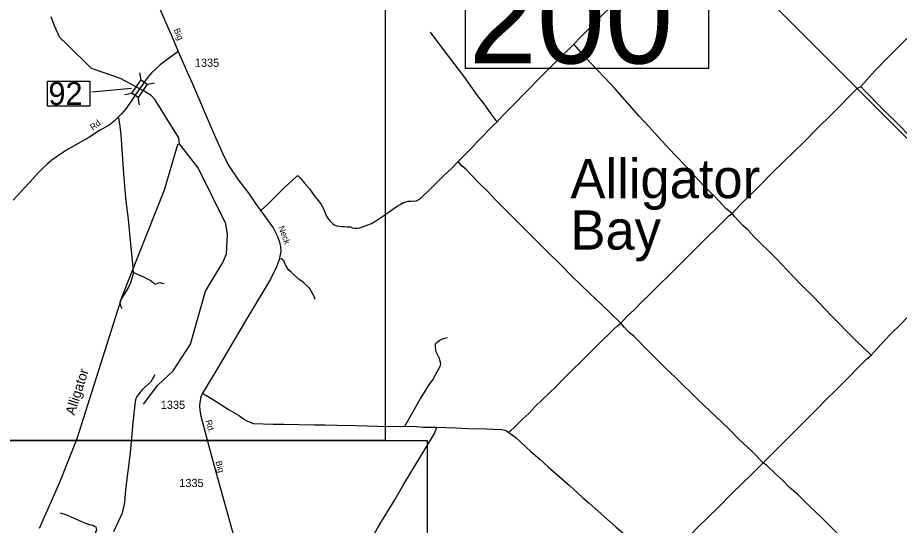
# Model space of a CAD drawing. Extents: x 2104537 to 2336408, y 34176 to 229611.
# Drawn here: x 2160349 to 2173826, y 123300 to 131059 of the extents above; entities that cross this region are included whole.
import ezdxf

# ---------------------------------------------------------------- set-up
doc = ezdxf.new("R2010")
doc.units = 0
for name, color, linetype in [('Exist Hydrographic Bay Label', 7, 'Continuous'), ('Exist Hydrographic Creek Single Shore', 7, 'Continuous'), ('Exist Hydrographic Misc Water Feature', 7, 'Continuous'), ('Exist Road Non-System Type 51', 7, 'Continuous'), ('Exist Road Secondary Structure Standard Bridge CELL', 7, 'Continuous'), ('Exist Road Secondary Structure Standard Bridge Number Label', 7, 'Continuous'), ('Exist Road Secondary Type 51 Attributed', 7, 'Continuous'), ('Exist Road Secondary Type 51 Label', 7, 'Continuous'), ('Exist Road Secondary Type 51 Number Label', 7, 'Continuous'), ('Exist Utilities Electrical Transmission Line', 7, 'Continuous'), ('Map Preparation Inset Cut Line', 7, 'Continuous'), ('Old_Level_32', 7, 'Continuous')]:
    doc.layers.add(name, color=color, linetype=linetype)

msp = doc.modelspace()

# ---------------------------------------------------------------- linework, layer by layer
at = {"layer": 'Exist Hydrographic Creek Single Shore'}
for points in [[(2162824, 129129), (2162812, 129223), (2162699, 129399), (2162453, 129802), (2162390, 129870), (2162282, 129937), (2161919, 130128), (2161480, 130281), (2161094, 130657), (2160995, 130756), (2160915, 130934), (2160861, 131074)], [(2160682, 123259), (2160994, 123961), (2161257, 124629), (2161945, 126800), (2162594, 128428), (2162799, 129120), (2162824, 129129)]]:
    msp.add_lwpolyline(points, dxfattribs=at)
at = {"layer": 'Exist Hydrographic Misc Water Feature'}
msp.add_lwpolyline([(2162271, 125150), (2162494, 125445), (2162726, 125663), (2162991, 126071), (2163219, 126881), (2163483, 127315), (2163541, 127449), (2163556, 127750), (2163530, 127908), (2163109, 128763), (2162824, 129129)], dxfattribs=at)
at = {"layer": 'Exist Road Non-System Type 51'}
for points in [[(2168849, 130656), (2168946, 130758), (2169084, 130892), (2169224, 131036), (2169477, 131283), (2169599, 131405), (2169858, 131652), (2169938, 131732), (2169974, 131760)], [(2173237, 130008), (2173449, 130246), (2173666, 130465), (2173780, 130585), (2174075, 130875), (2174161, 130965), (2174337, 131140), (2174389, 131188), (2174553, 131354), (2174594, 131391)], [(2167679, 129467), (2167587, 129587), (2167481, 129741), (2167380, 129869), (2167186, 130142), (2166779, 130678), (2166661, 130839)], [(2167679, 129467), (2167771, 129567), (2167970, 129766), (2168072, 129874), (2168393, 130203), (2168593, 130399), (2168849, 130656)], [(2171273, 128064), (2171176, 128144), (2171005, 128324), (2170933, 128390), (2170851, 128472), (2170763, 128571), (2170663, 128677), (2170583, 128767), (2170394, 128961), (2170192, 129184), (2170086, 129296), (2169998, 129396), (2169849, 129556), (2169481, 129971), (2169321, 130143), (2169210, 130254), (2169034, 130446), (2168849, 130656)], [(2171273, 128064), (2171391, 128200), (2171685, 128485), (2171894, 128697), (2172365, 129156), (2172571, 129363), (2172796, 129583), (2173181, 129975)], [(2173181, 129975), (2173185, 129980), (2173237, 130008)], [(2175369, 127892), (2175237, 128004), (2174529, 128709), (2174185, 129038), (2173845, 129395), (2173578, 129653), (2173292, 129944), (2173237, 130008)], [(2161893, 129528), (2161912, 129401), (2161925, 129269), (2161967, 128671), (2161994, 128369), (2162005, 128256), (2162037, 127982), (2162058, 127758), (2162106, 127298), (2162110, 127238), (2162109, 127196), (2162119, 127164)], [(2167084, 128860), (2167276, 129056), (2167376, 129167), (2167627, 129419), (2167679, 129467)], [(2164070, 128115), (2164170, 128204), (2164258, 128297), (2164426, 128461), (2164609, 128633), (2164621, 128643), (2164637, 128641), (2164667, 128613), (2164733, 128529), (2164816, 128438), (2164878, 128348), (2164964, 128240), (2164986, 128206), (2165022, 128138), (2165052, 128076), (2165072, 128026), (2165088, 127996), (2165123, 127954), (2165167, 127908), (2165185, 127892), (2165227, 127878), (2165297, 127868), (2165343, 127869), (2165387, 127863), (2165435, 127861), (2165469, 127849), (2165497, 127843), (2165547, 127841), (2165579, 127847), (2165704, 127892), (2165758, 127915), (2165810, 127942), (2165962, 128044), (2166046, 128106), (2166148, 128176), (2166194, 128206), (2166246, 128234), (2166316, 128255), (2166352, 128255), (2166394, 128259), (2166422, 128257), (2166448, 128261), (2166492, 128287), (2166621, 128401), (2166855, 128635), (2166923, 128702), (2166982, 128756), (2167084, 128860)], [(2169568, 126390), (2169267, 126683), (2169095, 126843), (2168822, 127110), (2168637, 127298), (2168462, 127465), (2167642, 128286), (2167526, 128413), (2167422, 128511), (2167272, 128665), (2167200, 128743), (2167140, 128793), (2167084, 128860)], [(2169568, 126390), (2169667, 126496), (2169771, 126594), (2169892, 126714), (2170000, 126824), (2170453, 127269), (2170852, 127670), (2171068, 127878), (2171154, 127966), (2171222, 128030), (2171273, 128064)], [(2173393, 125902), (2173157, 126130), (2172782, 126509), (2172508, 126799), (2172343, 126957), (2172201, 127102), (2171941, 127376), (2171600, 127715), (2171508, 127817), (2171432, 127885), (2171306, 128021), (2171273, 128064)], [(2173393, 125902), (2173485, 126004), (2173686, 126215), (2173858, 126385), (2174021, 126559), (2174271, 126804), (2174508, 127048), (2174706, 127247), (2174842, 127389), (2174929, 127475), (2174989, 127539), (2175133, 127679), (2175195, 127743), (2175261, 127804), (2175303, 127846)], [(2164896, 126753), (2164873, 126820), (2164810, 126925), (2164716, 127011), (2164654, 127059), (2164531, 127172), (2164489, 127206), (2164443, 127284), (2164420, 127345), (2164373, 127379)], [(2162119, 127164), (2162072, 127008), (2162047, 126948), (2162014, 126888), (2161980, 126837), (2161929, 126751), (2161917, 126725), (2161913, 126704), (2161918, 126669), (2161924, 126647), (2161942, 126615)], [(2162119, 127164), (2162274, 127100), (2162330, 127070), (2162374, 127045), (2162416, 127015), (2162441, 126989), (2162457, 126984), (2162502, 127004), (2162522, 127010), (2162552, 127002), (2162591, 126997)], [(2167855, 124721), (2167964, 124821), (2168058, 124915), (2168168, 125017), (2168260, 125115), (2168579, 125424), (2168697, 125546), (2169102, 125942), (2169208, 126051), (2169467, 126301), (2169525, 126355), (2169568, 126390)], [(2171744, 124258), (2171570, 124433), (2171378, 124613), (2171212, 124779), (2170745, 125222), (2170409, 125557), (2170238, 125719), (2170064, 125892), (2169996, 125956), (2169772, 126184), (2169690, 126254), (2169625, 126322), (2169568, 126390)], [(2166268, 124817), (2166504, 125228), (2166638, 125446), (2166696, 125526), (2166812, 125745), (2166818, 125773), (2166809, 125810), (2166791, 125862), (2166746, 125953), (2166742, 125991), (2166736, 126019), (2166738, 126073), (2166754, 126097), (2166803, 126132), (2166841, 126150), (2166920, 126170)], [(2171744, 124258), (2171876, 124390), (2171990, 124498), (2172554, 125065), (2172706, 125223), (2172844, 125356), (2172980, 125496), (2173267, 125782), (2173327, 125846), (2173393, 125902)], [(2162444, 125601), (2162387, 125495), (2162284, 125404), (2162244, 125360), (2162171, 125267), (2162155, 125241), (2162145, 125193), (2162109, 124866), (2162067, 124410), (2162000, 123847), (2161982, 123647), (2161969, 123571), (2161953, 123517), (2161948, 123485), (2161812, 123201)], [(2163188, 125310), (2163313, 125238), (2163580, 125068), (2163727, 124985), (2163818, 124920), (2163864, 124891), (2163956, 124857), (2164256, 124846), (2164416, 124848), (2164886, 124836), (2165042, 124835), (2165234, 124829), (2165528, 124826), (2165854, 124817), (2166204, 124812), (2166268, 124817)], [(2165682, 122845), (2165672, 122891), (2165680, 122935), (2165700, 122995), (2165742, 123071), (2165794, 123155), (2165855, 123265), (2166021, 123544), (2166115, 123692), (2166236, 123902), (2166722, 124705), (2166756, 124801)], [(2166268, 124817), (2166446, 124811), (2166540, 124803), (2166662, 124799), (2166756, 124801)], [(2166756, 124801), (2167046, 124792), (2167240, 124780), (2167516, 124776), (2167751, 124767), (2167794, 124757), (2167819, 124745), (2167855, 124721)], [(2167855, 124721), (2167969, 124637), (2168193, 124427), (2168332, 124312), (2168456, 124197), (2168786, 123910), (2168980, 123730), (2169085, 123637), (2169492, 123279), (2169976, 122859), (2170038, 122813), (2170121, 122739), (2170159, 122699)], [(2170159, 122699), (2170269, 122799), (2170387, 122919), (2170644, 123168), (2170740, 123266), (2171060, 123578), (2171275, 123795), (2171567, 124079), (2171744, 124258)], [(2173867, 122202), (2173755, 122318), (2173577, 122491), (2173387, 122689), (2173200, 122867), (2172774, 123282), (2172656, 123402), (2172441, 123603), (2172273, 123771), (2172149, 123877), (2172039, 123990), (2171937, 124082), (2171800, 124214), (2171744, 124258)], [(2161000, 123494), (2161094, 123459), (2161373, 123339), (2161463, 123306), (2161496, 123301), (2161519, 123287), (2161546, 123279), (2161554, 123233), (2161531, 123167), (2161478, 122984), (2161451, 122898), (2161401, 122750), (2161379, 122693), (2161326, 122563), (2161299, 122503), (2161256, 122418), (2161168, 122230), (2160944, 121739), (2160777, 121272), (2160720, 121101), (2160705, 121047)]]:
    msp.add_lwpolyline(points, dxfattribs=at)
at = {"layer": 'Exist Road Secondary Structure Standard Bridge CELL'}
for p, q in [((2162235, 130107), (2162215, 130218)), ((2162328, 130043), (2162440, 130063)), ((2161983, 129883), (2162094, 129903)), ((2162210, 129726), (2162189, 129838))]:
    msp.add_line(p, q, dxfattribs=at)
msp.add_lwpolyline([(2162094, 129903), (2162235, 130107), (2162330, 130042), (2162189, 129838)], close=True, dxfattribs=at)
at = {"layer": 'Exist Road Secondary Structure Standard Bridge Number Label'}
msp.add_line((2162088, 129975), (2161485, 129920), dxfattribs=at)
for points in [[(2167195, 131816), (2170910, 131816), (2170910, 130280), (2167195, 130280)], [(2160807, 130088), (2161451, 130088), (2161451, 129705), (2160807, 129705)]]:
    msp.add_lwpolyline(points, close=True, dxfattribs=at)
at = {"layer": 'Exist Road Secondary Type 51 Attributed'}
for points in [[(2162116, 132164), (2162163, 132029), (2162249, 131810), (2162413, 131453), (2162639, 130924), (2162732, 130713), (2162802, 130544)], [(2162802, 130544), (2162652, 130432), (2162527, 130338), (2162450, 130269), (2162400, 130221), (2162338, 130148), (2162214, 129973)], [(2162802, 130544), (2162944, 130214), (2163020, 130049), (2163353, 129272), (2163499, 128940), (2163576, 128795), (2163724, 128578), (2163881, 128370), (2163985, 128219), (2164257, 127846), (2164323, 127716), (2164352, 127628), (2164368, 127559), (2164371, 127483), (2164348, 127364), (2164312, 127259), (2164214, 127064), (2163830, 126425), (2163438, 125757), (2163168, 125308), (2163150, 125263), (2163139, 125206), (2163130, 125133), (2163133, 125053), (2163150, 124969), (2163329, 124302), (2163981, 121959)], [(2162214, 129973), (2162125, 129845), (2162010, 129672), (2161938, 129588), (2161878, 129527), (2161824, 129476), (2161749, 129417), (2161601, 129336), (2161437, 129230), (2161237, 129116), (2161085, 129030), (2161004, 128973), (2160870, 128883), (2160793, 128813), (2160735, 128760), (2160661, 128687), (2160588, 128600), (2160279, 128271)]]:
    msp.add_lwpolyline(points, dxfattribs=at)
at = {"layer": 'Exist Utilities Electrical Transmission Line'}
for points in [[(2173181, 129975), (2172029, 131127), (2171480, 131664)], [(2175303, 127846), (2175249, 127900), (2174612, 128544), (2173181, 129975)]]:
    msp.add_lwpolyline(points, dxfattribs=at)
at = {"layer": 'Map Preparation Inset Cut Line'}
for points in [[(2165966, 124595), (2135584, 124595), (2135584, 153500), (2165966, 153500)], [(2163450, 80447), (2123592, 80447), (2123592, 124595), (2166610, 124595), (2166610, 99632), (2163450, 99632)]]:
    msp.add_lwpolyline(points, close=True, dxfattribs=at)

# ---------------------------------------------------------------- texts
at = {"layer": 'Exist Hydrographic Bay Label'}
for s, p in [('Alligator', (2168799, 128300)), ('Bay', (2168799, 127514))]:
    msp.add_text(s, height=600, dxfattribs=at).set_placement(p)
at = {"layer": 'Exist Road Secondary Structure Standard Bridge Number Label'}
for s, height, p in [('200', 1400, (2167245, 130359)), ('92', 350, (2160820, 129725))]:
    msp.add_text(s, height=height, dxfattribs=at).set_placement(p)
at = {"layer": 'Exist Road Secondary Type 51 Label'}
for s, rotation, p in [('Big', 294.0672, (2162731, 130872)), ('Rd.', 37.1948, (2161500, 129332)), ('Neck', 290.6954, (2164331, 127856)), ('Rd.', 285.4463, (2163220, 124899)), ('Big', 285.4463, (2163372, 124274))]:
    msp.add_text(s, height=95, rotation=rotation, dxfattribs=at).set_placement(p)
at = {"layer": 'Exist Road Secondary Type 51 Number Label'}
for p in [(2163058, 130308), (2162537, 125080), (2162819, 123886)]:
    msp.add_text('1335', height=125, dxfattribs=at).set_placement(p)
at = {"layer": 'Old_Level_32'}
msp.add_text('Alligator', height=150, rotation=72.1875, dxfattribs=at).set_placement((2161217, 124975))

doc.saveas('drawing.dxf')
